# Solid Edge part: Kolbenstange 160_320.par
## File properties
Username: ahadarics
Dokumentum tartalom típus: 0
Author: ahadarics
Last saved by: ahadarics
Revision: 89
Sűrűség: 0,000 kg/m^3
Pontosság: 0,990
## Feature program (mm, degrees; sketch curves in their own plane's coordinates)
base feature "unnamed BaseFeature 1"
thread "unnamed Thread 1"
chamfer "Letörés_1"  SetBackValue2 = 25 deg
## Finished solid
Body 1: solid body, 22 faces, 30 edges, 11 vertices.
  Faces by surface: plane 8, cone 5, cylinder 5, torus 4
  Edges by curve: circle 18, line 7, curve on surface 3, ellipse 2
Bounding box of the edges (mm; curved faces can reach further): 161.600 x 161.600 x 602.000, from (-80.8, -80.8, -173.5) to (80.8, 80.8, 428.5).
Cylindrical faces by radius (mm): R16.4 x1, R18 x1, R19.5 x1, R20 x1, R80 x1
Conical faces (half-angle, radius in mm at the cone's reference point): 25 deg R18 x1, 30 deg R19.567 x1, 30 deg R19.75 x1, 45 deg R79.25 x1, 60 deg R17.2 x1
Toroidal faces (ring radius, tube radius in mm): R17.2 r0.8 x2, R17.7 r1.8 x1, R80.8 r0.8 x1
Planar faces by outward normal: +x 1, +z 3, -x 1, -z 1, oblique 2
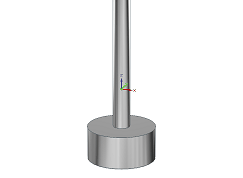
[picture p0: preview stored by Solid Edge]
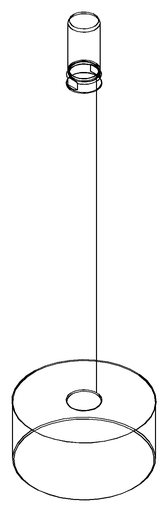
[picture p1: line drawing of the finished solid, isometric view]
